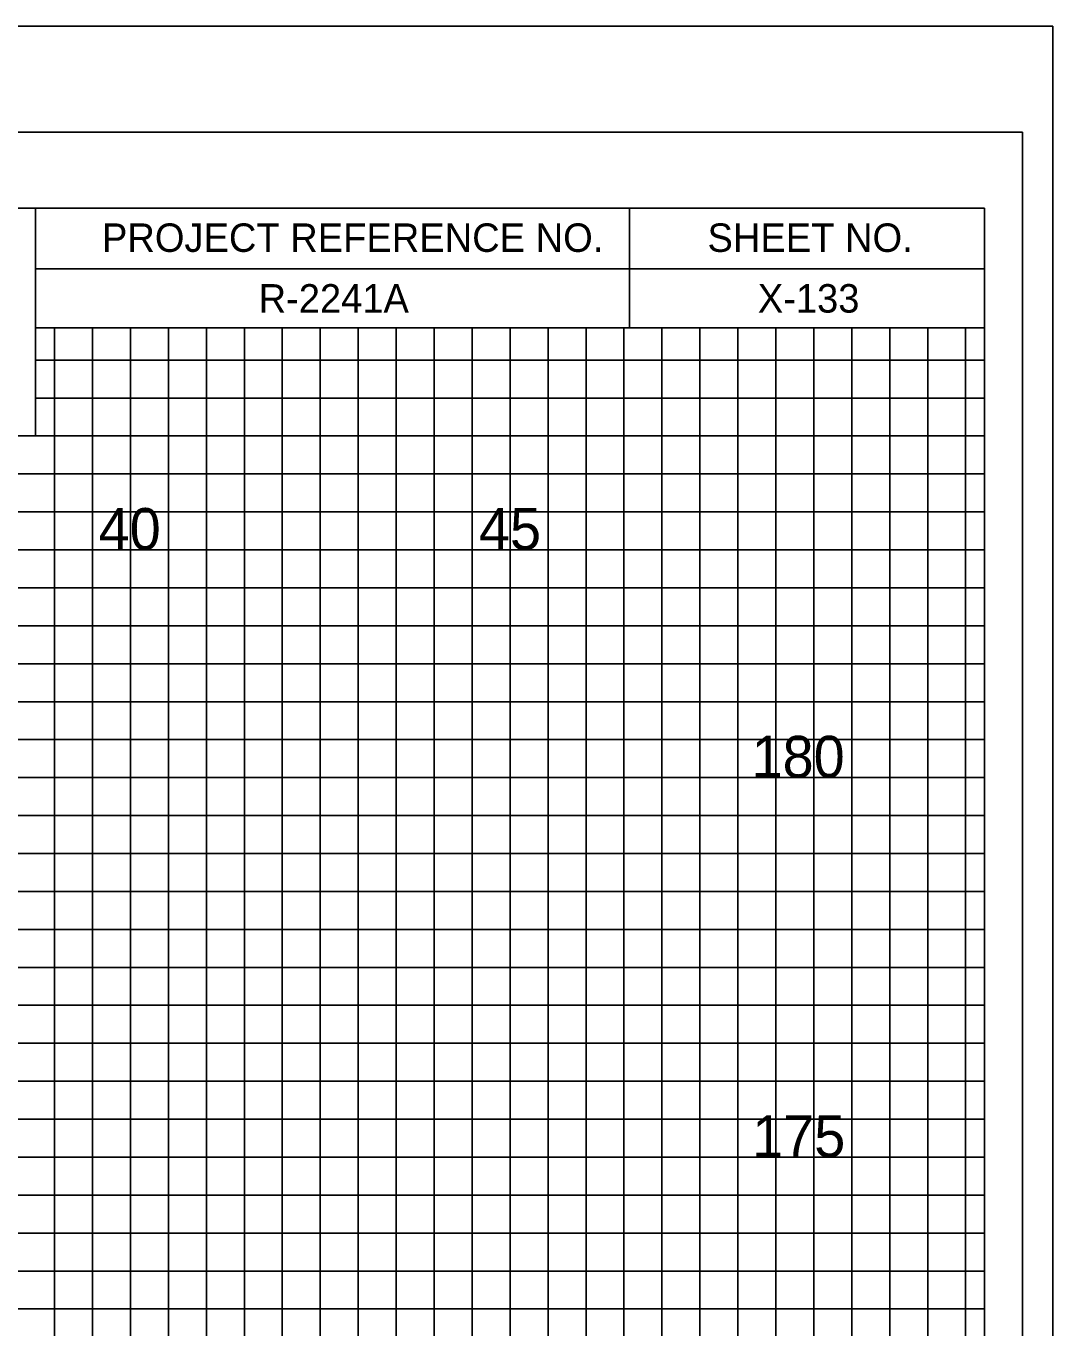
# Model space of a CAD drawing. Extents: x -4 to 103, y -2 to 280.
# Drawn here: x 89.87 to 103.4, y 121.08 to 138.22 of the extents above; entities that cross this region are included whole.
import ezdxf

# ---------------------------------------------------------------- set-up
doc = ezdxf.new("R2010")
doc.units = 0
for name, color, linetype in [('Exist XS Center Line Elevation Label', 7, 'Continuous'), ('Old_Level_63', 7, 'Continuous'), ('Prop XS Dump Level', 7, 'Continuous'), ('Prop XS Pvmt Edge Slope', 7, 'Continuous'), ('Prop XS SE Text', 7, 'Continuous'), ('Prop XS Side Slope Text', 7, 'Continuous'), ('Prop XS SS Elevation Text', 7, 'Continuous'), ('Prop XS Subgrade Earthwork', 7, 'Continuous'), ('Sheet Cutting Line CELL', 7, 'Continuous'), ('Sheet Plot Border Inside CELL', 7, 'Continuous'), ('Sheet Plot Border Outside CELL', 7, 'Continuous')]:
    doc.layers.add(name, color=color, linetype=linetype)

msp = doc.modelspace()

# ---------------------------------------------------------------- linework, layer by layer
at = {"layer": 'Exist XS Center Line Elevation Label'}
for points in [[(91.25, 70.825), (91.25, 134.25), (93.75, 134.25), (93.75, 70.825)], [(96.25, 70.825), (96.25, 134.25), (98.75, 134.25), (98.75, 70.825)], [(101.25, 70.825), (101.25, 134.25)], [(90, 133.325), (102.5, 133.325)], [(0, 128.325), (102.5, 128.325), (102.5, 130.825), (0, 130.825)], [(0, 123.325), (102.5, 123.325), (102.5, 125.825), (0, 125.825)]]:
    msp.add_lwpolyline(points, dxfattribs=at)
at = {"layer": 'Old_Level_63'}
for p, q in [((90, 135.825), (102.5, 135.825)), ((90, 135.825), (102.5, 135.825)), ((97.825, 134.25), (97.825, 135.825)), ((101.875, 135.825), (101.875, 135.825)), ((102.5, 135.825), (102.5, 135.825)), ((102.5, 134.25), (102.5, 135.825)), ((102.5, 135.825), (102.5, 135.825)), ((102.5, 135.825), (102.5, 135.825)), ((102.5, 134.25), (102.5, 135.825)), ((90, 135.025), (102.5, 135.025)), ((90, 134.25), (102.5, 134.25)), ((99.4, 134.25), (99.4, 134.25)), ((99.4, 134.25), (99.4, 134.25))]:
    msp.add_line(p, q, dxfattribs=at)
for points in [[(102.5, 135.825), (0, 135.825), (0, 70.825), (102.5, 70.825)], [(83.75, 135.825), (90, 135.825), (90, 132.825), (83.75, 132.825)]]:
    msp.add_lwpolyline(points, close=True, dxfattribs=at)
at = {"layer": 'Prop XS Dump Level'}
for p, q in [((91.25, 70.825), (91.25, 134.25)), ((93.75, 70.825), (93.75, 134.25)), ((96.25, 70.825), (96.25, 134.25)), ((98.75, 70.825), (98.75, 134.25)), ((101.25, 70.825), (101.25, 134.25)), ((90, 133.325), (102.5, 133.325)), ((0, 130.825), (102.5, 130.825)), ((0, 128.325), (102.5, 128.325)), ((0, 125.825), (102.5, 125.825)), ((0, 123.325), (102.5, 123.325))]:
    msp.add_line(p, q, dxfattribs=at)
at = {"layer": 'Prop XS SE Text'}
for points in [[(90.25, 70.825), (90.25, 134.25), (90.75, 134.25), (90.75, 70.825)], [(91.75, 70.825), (91.75, 134.25), (92.25, 134.25), (92.25, 70.825)], [(92.75, 70.825), (92.75, 134.25), (93.25, 134.25), (93.25, 70.825)], [(94.25, 70.825), (94.25, 134.25), (94.75, 134.25), (94.75, 70.825)], [(95.25, 70.825), (95.25, 134.25), (95.75, 134.25), (95.75, 70.825)], [(96.75, 70.825), (96.75, 134.25), (97.25, 134.25), (97.25, 70.825)], [(97.75, 70.825), (97.75, 134.25), (98.25, 134.25), (98.25, 70.825)], [(99.25, 70.825), (99.25, 134.25), (99.75, 134.25), (99.75, 70.825)], [(100.25, 70.825), (100.25, 134.25)], [(100.25, 134.25), (100.75, 134.25), (100.75, 70.825), (101.75, 70.825), (101.75, 134.25), (102.25, 134.25), (102.25, 70.825)], [(102.5, 132.825), (102.5, 133.825), (90, 133.825)], [(0, 132.325), (102.5, 132.325), (102.5, 132.825), (0, 132.825)], [(0, 131.325), (102.5, 131.325), (102.5, 131.825), (0, 131.825)], [(0, 129.825), (102.5, 129.825), (102.5, 130.325), (0, 130.325)], [(0, 128.825), (102.5, 128.825), (102.5, 129.325), (0, 129.325)], [(0, 127.325), (102.5, 127.325), (102.5, 127.825), (0, 127.825)], [(0, 126.325), (102.5, 126.325), (102.5, 126.825), (0, 126.825)], [(0, 124.825), (102.5, 124.825), (102.5, 125.325), (0, 125.325)], [(0, 123.825), (102.5, 123.825), (102.5, 124.325), (0, 124.325)], [(0, 122.325), (102.5, 122.325), (102.5, 122.825), (0, 122.825)], [(0, 121.325), (102.5, 121.325), (102.5, 121.825), (0, 121.825)]]:
    msp.add_lwpolyline(points, dxfattribs=at)
at = {"layer": 'Sheet Cutting Line CELL'}
msp.add_line((-3.5, 138.225), (103.4, 138.225), dxfattribs=at)
at = {"layer": 'Sheet Plot Border Inside CELL'}
msp.add_lwpolyline([(103, 136.825), (-2.8, 136.825), (-2.8, 69.825), (103, 69.825)], close=True, dxfattribs=at)
at = {"layer": 'Sheet Plot Border Outside CELL'}
msp.add_lwpolyline([(103.4, 138.225), (-3.5, 138.225), (-3.5, 68.4), (103.4, 68.4)], close=True, dxfattribs=at)

# ---------------------------------------------------------------- texts
at = {"layer": 'Old_Level_63'}
for s, p in [('PROJECT REFERENCE NO.', (90.875, 135.25)), ('SHEET NO.', (98.85, 135.25))]:
    msp.add_text(s, height=0.375, dxfattribs=at).set_placement(p)
at = {"layer": 'Prop XS Pvmt Edge Slope'}
for s, p in [('40', (90.831, 131.325)), ('45', (95.84, 131.325))]:
    msp.add_text(s, height=0.55, dxfattribs=at).set_placement(p)
at = {"layer": 'Prop XS Side Slope Text'}
msp.add_text('X-133', height=0.375, dxfattribs=at).set_placement((99.513, 134.45))
at = {"layer": 'Prop XS SS Elevation Text'}
msp.add_text('R-2241A', height=0.375, dxfattribs=at).set_placement((92.938, 134.45))
at = {"layer": 'Prop XS Subgrade Earthwork'}
for s, p in [('180', (99.43, 128.325)), ('175', (99.438, 123.325))]:
    msp.add_text(s, height=0.55, dxfattribs=at).set_placement(p)

doc.saveas('drawing.dxf')
